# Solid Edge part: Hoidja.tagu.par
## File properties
Author: Türk
Template: Iso Part.par
Last saved by: Türk
Revision: 21
Application: Solid Edge
Accuracy: 0,990
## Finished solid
Body 1: sheet body, 1 face, 7 edges, 4 vertices.
  Faces by surface: plane 1
  Edges by curve: line 4, circle 3
Body 2: solid body, 33 faces, 86 edges, 48 vertices.
  Faces by surface: cylinder 18, plane 15
  Edges by curve: line 50, circle 36
Bounding box of the edges (mm): 725.214 x 50.000 x 725.214, from (-313.8854, 0, -362.6068) to (411.3282, 50, 362.6068).
Cylindrical faces by radius (mm): R4 x2, R5 x4, R10 x2, R10.5 x4, R15 x1, R25 x4, R40 x1
Planar faces by outward normal: +x 5, +y 1, +z 2, -x 3, -y 1, -z 3
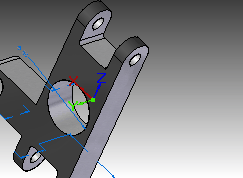
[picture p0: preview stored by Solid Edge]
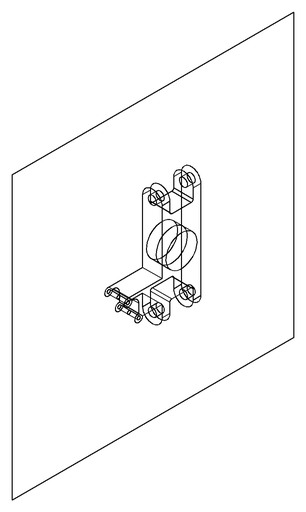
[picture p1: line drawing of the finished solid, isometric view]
